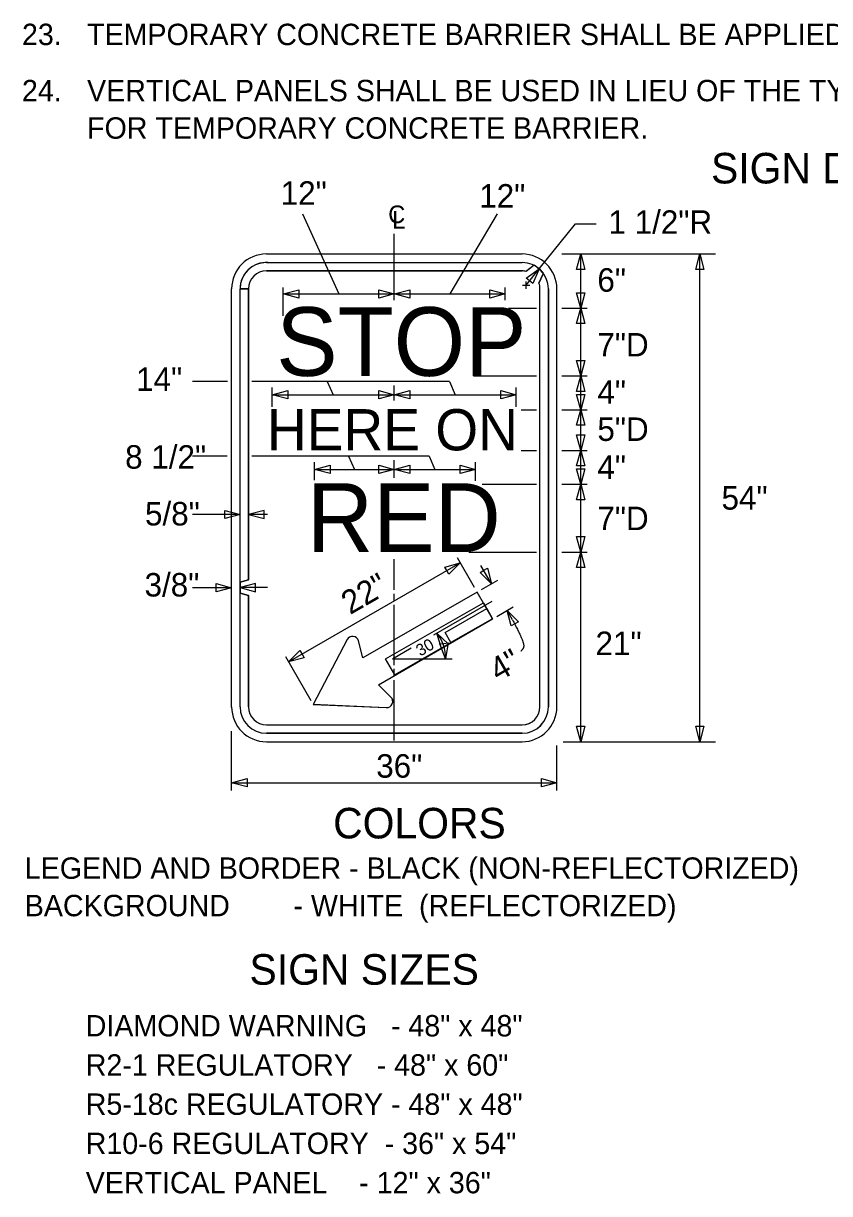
# Model space of a CAD drawing. Extents: x 16520 to 18479, y 5662 to 6927.
# Drawn here: x 17776.7 to 18093.2, y 5956.3 to 6415.8 of the extents above; entities that cross this region are included whole.
import ezdxf

# ---------------------------------------------------------------- set-up
doc = ezdxf.new("R2010")
doc.units = 0
for name, color, linetype in [('MT_SCRATCH_LEVEL_A', 7, 'Continuous'), ('TRAFFIC_SIGNS_PR', 7, 'Continuous'), ('TYPICAL_TEXT_DIMEN_EX', 7, 'Continuous'), ('TYPICAL_TEXT_DIMEN_PR', 7, 'Continuous')]:
    doc.layers.add(name, color=color, linetype=linetype)

msp = doc.modelspace()

# ---------------------------------------------------------------- linework, layer by layer
at = {"layer": 'MT_SCRATCH_LEVEL_A'}
for p, q in [((17922.3, 6307.14), (17922.3, 6333.18)), ((17922.3, 6267.68), (17922.3, 6273.69)), ((17922.3, 6237.32), (17922.3, 6244.25)), ((17922.3, 6193.35), (17922.3, 6205.49)), ((17922.3, 6188.92), (17922.3, 6191.87)), ((17922.3, 6163.79), (17922.3, 6187.44)), ((17922.3, 6159.36), (17922.3, 6162.32)), ((17922.3, 6134.24), (17922.3, 6157.88))]:
    msp.add_line(p, q, dxfattribs=at)
at = {"layer": 'TRAFFIC_SIGNS_PR'}
for p, q in [((17872.12, 6325.27), (17972.55, 6325.27)), ((17872.12, 6321.95), (17872.65, 6321.95)), ((17872.12, 6318.62), (17972.57, 6318.62)), ((17972.57, 6318.62), (17872.12, 6318.62)), ((17872.65, 6321.95), (17972.47, 6321.95)), ((17872.65, 6321.93), (17972.47, 6321.95)), ((17977.27, 6320.83), (17974.08, 6318.36)), ((17977.27, 6320.83), (17974.33, 6318.69)), ((17979.08, 6313.77), (17980.85, 6317.7)), ((17980.62, 6317.24), (17979.08, 6313.77)), ((17858.46, 6147.28), (17858.46, 6311.6)), ((17861.78, 6311.6), (17865.1, 6311.6)), ((17865.11, 6311.6), (17861.78, 6311.6)), ((17861.78, 6147.42), (17861.78, 6311.53)), ((17865.1, 6311.53), (17861.78, 6311.53)), ((17865.1, 6197.27), (17865.1, 6311.53)), ((17979.48, 6147.42), (17979.48, 6311.6)), ((17979.48, 6147.42), (17979.48, 6311.6)), ((17982.81, 6147.42), (17982.81, 6311.6)), ((17982.81, 6311.6), (17982.81, 6147.42)), ((17986.14, 6147.42), (17986.14, 6311.6)), ((17861.79, 6196.38), (17865.1, 6197.27)), ((17861.79, 6193.07), (17861.79, 6195.38)), ((17865.1, 6191.18), (17861.79, 6192.07)), ((17865.1, 6147.42), (17865.1, 6191.18)), ((17954.82, 6192.53), (17910.01, 6166.66)), ((17960.9, 6182), (17954.82, 6192.53)), ((17916.09, 6156.13), (17960.9, 6182)), ((17903.76, 6173.84), (17890.48, 6148.36)), ((17910.01, 6166.66), (17908.27, 6173.33)), ((17920.99, 6151.28), (17916.09, 6156.13)), ((17890.48, 6148.36), (17919.18, 6147.13)), ((17872.12, 6140.4), (17972.52, 6140.4)), ((17872.12, 6140.4), (17972.52, 6140.4)), ((17872.12, 6137.08), (17972.47, 6137.08)), ((17972.47, 6137.08), (17872.12, 6137.08)), ((17872.12, 6133.75), (17930.99, 6133.75)), ((17872.12, 6133.75), (17930.99, 6133.75)), ((17930.99, 6133.75), (17972.47, 6133.75))]:
    msp.add_line(p, q, dxfattribs=at)
msp.add_lwpolyline([(17861.78, 6147.42), (17861.78, 6311.53), (17865.1, 6311.53), (17865.1, 6197.27), (17861.79, 6196.38), (17861.79, 6192.07), (17865.1, 6191.18), (17865.1, 6147.42)], dxfattribs=at)
for points in [[(17960.9, 6182), (17922.52, 6160.01), (17918.9, 6166.33), (17957.28, 6188.32)], [(17960.9, 6182), (17944.56, 6172.65), (17942.24, 6176.7), (17958.58, 6186.05)]]:
    msp.add_lwpolyline(points, close=True, dxfattribs=at)
for centre, radius, start, end in [((17872.12, 6311.6), 13.67, 90, 180), ((17972.46, 6311.6), 13.67, 0, 90), ((17872.12, 6311.6), 10.34, 90, 180), ((17872.12, 6311.6), 10.34, 87.0749, 180), ((17872.12, 6311.6), 7.02, 90, 180), ((17872.12, 6311.6), 7.02, 90, 180), ((17972.46, 6311.6), 10.34, 0.0011, 90), ((17972.46, 6311.6), 10.34, 0, 90), ((17972.46, 6311.6), 7.02, 76.1968, 90), ((17972.68, 6314.86), 3.76, 68.3136, 91.7829), ((17965.42, 6303.66), 20.86, 42.2917, 55.3821), ((17972.46, 6311.6), 10.34, 42.6036, 55.6914), ((17975.26, 6311.94), 4.24, 355.4085, 25.5399), ((17972.46, 6311.6), 7.02, 0.0011, 18.4463), ((17905.91, 6172.71), 2.43, 14.678, 152.4708), ((17919.28, 6149.56), 2.43, 267.5292, 45.322), ((17872.12, 6147.42), 13.67, 180, 270), ((17872.12, 6147.42), 10.34, 180, 270), ((17872.12, 6147.42), 10.35, 180, 270), ((17872.12, 6147.42), 7.02, 180, 270), ((17872.12, 6147.42), 7.02, 180, 270), ((17972.46, 6147.42), 10.34, 270, 0), ((17972.46, 6147.42), 7.02, 270, 0), ((17972.46, 6147.42), 13.67, 270, 0), ((17972.46, 6147.42), 10.35, 270, 0), ((17972.46, 6147.42), 7.02, 270.4693, 0)]:
    msp.add_arc(centre, radius, start, end, dxfattribs=at)
at = {"layer": 'TYPICAL_TEXT_DIMEN_EX'}
for p, q in [((17903.76, 6173.84), (17890.48, 6148.36)), ((17910.01, 6166.66), (17908.27, 6173.33)), ((17916.1, 6156.13), (17921, 6151.28)), ((17919.18, 6147.12), (17890.48, 6148.36))]:
    msp.add_line(p, q, dxfattribs=at)
for centre, start, end in [((17905.91, 6172.71), 14.6782, 152.471), ((17919.29, 6149.56), 267.5295, 45.3222)]:
    msp.add_arc(centre, 2.43, start, end, dxfattribs=at)
at = {"layer": 'TYPICAL_TEXT_DIMEN_PR'}
for p, q in [((17886.21, 6341.01), (17900.52, 6309.57)), ((17962.76, 6341.01), (17944.07, 6309.57)), ((17979.22, 6319.44), (17993.5, 6337.13)), ((17993.5, 6337.13), (18001.59, 6337.13)), ((17988.05, 6325.27), (18048.37, 6325.27)), ((17993.87, 6319.2), (17995.5, 6325.27)), ((17995.5, 6303.99), (17995.5, 6325.27)), ((17995.5, 6325.27), (17997.12, 6319.2)), ((18040.65, 6319.2), (18042.27, 6325.27)), ((18042.27, 6133.75), (18042.27, 6325.27)), ((18042.27, 6325.27), (18043.9, 6319.2)), ((17974.06, 6313.04), (17979.22, 6319.44)), ((17974.15, 6315.74), (17979.22, 6319.44)), ((17979.22, 6319.44), (17976.68, 6313.69)), ((17995.5, 6319.2), (17993.87, 6319.2)), ((17997.12, 6319.2), (17995.5, 6319.2)), ((18042.27, 6319.2), (18040.65, 6319.2)), ((18043.9, 6319.2), (18042.27, 6319.2)), ((17974.06, 6311.56), (17974.06, 6314.51)), ((17975.41, 6314.71), (17974.15, 6315.74)), ((17976.68, 6313.69), (17975.41, 6314.71)), ((17878.74, 6300.98), (17878.74, 6312.05)), ((17878.74, 6309.57), (17884.8, 6311.19)), ((17878.74, 6309.57), (17922.3, 6309.57)), ((17884.8, 6307.94), (17878.74, 6309.57)), ((17884.8, 6311.19), (17884.8, 6309.57)), ((17884.8, 6309.57), (17884.8, 6307.94)), ((17916.23, 6309.57), (17916.23, 6311.19)), ((17916.23, 6311.19), (17922.3, 6309.57)), ((17922.3, 6309.57), (17916.23, 6307.94)), ((17916.23, 6307.94), (17916.23, 6309.57)), ((17922.3, 6309.57), (17928.36, 6311.19)), ((17922.3, 6309.57), (17965.85, 6309.57)), ((17928.36, 6307.94), (17922.3, 6309.57)), ((17928.36, 6311.19), (17928.36, 6309.57)), ((17928.36, 6309.57), (17928.36, 6307.94)), ((17959.78, 6309.57), (17959.78, 6311.19)), ((17959.78, 6311.19), (17965.85, 6309.57)), ((17959.78, 6309.57), (17959.78, 6311.19)), ((17959.78, 6311.19), (17965.85, 6309.57)), ((17965.85, 6309.57), (17959.78, 6307.94)), ((17959.78, 6307.94), (17959.78, 6309.57)), ((17965.85, 6309.57), (17959.78, 6307.94)), ((17959.78, 6307.94), (17959.78, 6309.57)), ((17965.85, 6307.14), (17965.85, 6312.05)), ((17972.58, 6313.04), (17975.54, 6313.04)), ((17995.5, 6303.99), (17993.87, 6310.06)), ((17993.87, 6310.06), (17995.5, 6310.06)), ((17995.5, 6310.06), (17997.12, 6310.06)), ((17997.12, 6310.06), (17995.5, 6303.99)), ((17967.19, 6303.99), (17978.2, 6303.99)), ((17988.05, 6303.99), (17997.98, 6303.99)), ((17993.87, 6297.93), (17995.5, 6303.99)), ((17995.5, 6277.39), (17995.5, 6303.99)), ((17995.5, 6303.99), (17997.12, 6297.93)), ((17995.5, 6297.93), (17993.87, 6297.93)), ((17997.12, 6297.93), (17995.5, 6297.93)), ((17995.5, 6277.39), (17993.87, 6283.46)), ((17993.87, 6283.46), (17995.5, 6283.46)), ((17995.5, 6283.46), (17997.12, 6283.46)), ((17997.12, 6283.46), (17995.5, 6277.39)), ((17953.45, 6277.39), (17978.2, 6277.39)), ((17988.05, 6277.39), (17997.98, 6277.39)), ((17993.87, 6271.32), (17995.5, 6277.39)), ((17995.5, 6264.09), (17995.5, 6277.39)), ((17995.5, 6277.39), (17997.12, 6271.32)), ((17856.87, 6275.15), (17843.07, 6275.15)), ((17944.01, 6275.15), (17866.39, 6275.15)), ((17874.42, 6265.2), (17874.42, 6272.87)), ((17895.99, 6275.15), (17898.35, 6270.01)), ((17944.01, 6275.15), (17946.23, 6270.01)), ((17970.17, 6265.2), (17970.17, 6272.87)), ((17874.42, 6270.01), (17880.48, 6271.64)), ((17874.42, 6270.01), (17922.3, 6270.01)), ((17880.48, 6268.39), (17874.42, 6270.01)), ((17880.48, 6271.64), (17880.48, 6270.01)), ((17880.48, 6270.01), (17880.48, 6268.39)), ((17916.23, 6270.01), (17916.23, 6271.64)), ((17916.23, 6271.64), (17922.3, 6270.01)), ((17922.3, 6270.01), (17916.23, 6268.39)), ((17916.23, 6268.39), (17916.23, 6270.01)), ((17922.3, 6270.01), (17928.36, 6271.64)), ((17922.3, 6270.01), (17970.17, 6270.01)), ((17928.36, 6268.39), (17922.3, 6270.01)), ((17928.36, 6271.64), (17928.36, 6270.01)), ((17928.36, 6270.01), (17928.36, 6268.39)), ((17964.11, 6270.01), (17964.11, 6271.64)), ((17964.11, 6271.64), (17970.17, 6270.01)), ((17970.17, 6270.01), (17964.11, 6268.39)), ((17964.11, 6268.39), (17964.11, 6270.01)), ((17995.5, 6271.32), (17993.87, 6271.32)), ((17995.5, 6264.09), (17993.87, 6270.16)), ((17993.87, 6270.16), (17995.5, 6270.16)), ((17997.12, 6271.32), (17995.5, 6271.32)), ((17995.5, 6270.16), (17997.12, 6270.16)), ((17997.12, 6270.16), (17995.5, 6264.09)), ((17972.18, 6264.09), (17978.2, 6264.09)), ((17988.05, 6264.09), (17997.98, 6264.09)), ((17993.87, 6258.03), (17995.5, 6264.09)), ((17995.5, 6248.13), (17995.5, 6264.09)), ((17995.5, 6264.09), (17997.12, 6258.03)), ((17995.5, 6258.03), (17993.87, 6258.03)), ((17995.5, 6248.13), (17993.87, 6254.2)), ((17993.87, 6254.2), (17995.5, 6254.2)), ((17997.12, 6258.03), (17995.5, 6258.03)), ((17995.5, 6254.2), (17997.12, 6254.2)), ((17997.12, 6254.2), (17995.5, 6248.13)), ((17856.7, 6245.88), (17843.07, 6245.88)), ((17936, 6245.88), (17866.39, 6245.88)), ((17904.28, 6245.88), (17906.67, 6240.67)), ((17936, 6245.88), (17938.26, 6240.67)), ((17972.18, 6248.13), (17978.2, 6248.13)), ((17988.05, 6248.13), (17997.98, 6248.13)), ((17993.87, 6242.07), (17995.5, 6248.13)), ((17995.5, 6234.83), (17995.5, 6248.13)), ((17995.5, 6248.13), (17997.12, 6242.07)), ((17891.04, 6236.44), (17891.04, 6243.53)), ((17891.04, 6240.67), (17897.11, 6242.3)), ((17891.04, 6240.67), (17922.3, 6240.67)), ((17897.11, 6239.05), (17891.04, 6240.67)), ((17897.11, 6242.3), (17897.11, 6240.67)), ((17897.11, 6240.67), (17897.11, 6239.05)), ((17916.23, 6240.67), (17916.23, 6242.3)), ((17916.23, 6242.3), (17922.3, 6240.67)), ((17922.3, 6240.67), (17916.23, 6239.05)), ((17916.23, 6239.05), (17916.23, 6240.67)), ((17922.3, 6240.67), (17928.36, 6242.3)), ((17922.3, 6240.67), (17954.22, 6240.67)), ((17928.36, 6239.05), (17922.3, 6240.67)), ((17928.36, 6242.3), (17928.36, 6240.67)), ((17928.36, 6240.67), (17928.36, 6239.05)), ((17948.15, 6240.67), (17948.15, 6242.3)), ((17948.15, 6242.3), (17954.22, 6240.67)), ((17954.22, 6240.67), (17948.15, 6239.05)), ((17948.15, 6239.05), (17948.15, 6240.67)), ((17954.22, 6236.22), (17954.22, 6243.53)), ((17995.5, 6242.07), (17993.87, 6242.07)), ((17995.5, 6234.83), (17993.87, 6240.9)), ((17993.87, 6240.9), (17995.5, 6240.9)), ((17997.12, 6242.07), (17995.5, 6242.07)), ((17995.5, 6240.9), (17997.12, 6240.9)), ((17997.12, 6240.9), (17995.5, 6234.83)), ((17956.81, 6234.83), (17978.2, 6234.83)), ((17988.05, 6234.83), (17997.98, 6234.83)), ((17993.87, 6228.77), (17995.5, 6234.83)), ((17995.5, 6208.23), (17995.5, 6234.83)), ((17995.5, 6234.83), (17997.12, 6228.77)), ((17995.5, 6228.77), (17993.87, 6228.77)), ((17997.12, 6228.77), (17995.5, 6228.77)), ((17861.79, 6222.98), (17843.07, 6222.98)), ((17855.72, 6222.98), (17855.72, 6224.6)), ((17855.72, 6224.6), (17861.79, 6222.98)), ((17861.79, 6222.98), (17855.72, 6221.35)), ((17855.72, 6221.35), (17855.72, 6222.98)), ((17871.17, 6224.6), (17865.1, 6222.98)), ((17865.1, 6222.98), (17871.17, 6221.35)), ((17872.58, 6222.98), (17865.1, 6222.98)), ((17871.17, 6222.98), (17871.17, 6224.6)), ((17871.17, 6221.35), (17871.17, 6222.98)), ((17995.5, 6208.23), (17993.87, 6214.3)), ((17993.87, 6214.3), (17995.5, 6214.3)), ((17995.5, 6214.3), (17997.12, 6214.3)), ((17997.12, 6214.3), (17995.5, 6208.23)), ((17951.55, 6208.23), (17978.2, 6208.23)), ((17988.05, 6208.23), (17997.98, 6208.23)), ((17993.87, 6202.17), (17995.5, 6208.23)), ((17995.5, 6133.75), (17995.5, 6208.23)), ((17995.5, 6208.23), (17997.12, 6202.17)), ((17880.83, 6165.08), (17948.21, 6203.98)), ((17942.14, 6202.36), (17948.21, 6203.98)), ((17948.21, 6203.98), (17943.77, 6199.54)), ((17953.8, 6194.3), (17947.08, 6205.94)), ((17942.95, 6200.95), (17942.14, 6202.36)), ((17943.77, 6199.54), (17942.95, 6200.95)), ((17956.05, 6200.25), (17957.46, 6201.06)), ((17960.49, 6195.81), (17956.05, 6200.25)), ((17960.49, 6195.81), (17956.33, 6203.01)), ((17957.46, 6201.06), (17958.87, 6201.88)), ((17958.87, 6201.88), (17960.49, 6195.81)), ((17995.5, 6202.17), (17993.87, 6202.17)), ((17997.12, 6202.17), (17995.5, 6202.17)), ((17858.46, 6194.24), (17843.07, 6194.24)), ((17852.39, 6194.24), (17852.39, 6195.86)), ((17852.39, 6195.86), (17858.46, 6194.24)), ((17858.46, 6194.24), (17852.39, 6192.61)), ((17852.39, 6192.61), (17852.39, 6194.24)), ((17867.86, 6195.91), (17861.79, 6194.28)), ((17861.79, 6194.28), (17867.86, 6192.66)), ((17872.58, 6194.28), (17861.79, 6194.28)), ((17867.86, 6194.28), (17867.86, 6195.91)), ((17867.86, 6192.66), (17867.86, 6194.28)), ((17956.5, 6193.5), (17962.9, 6197.2)), ((17937.82, 6175.7), (17960.7, 6188.91)), ((17962.58, 6182.97), (17968.98, 6186.66)), ((17968.66, 6181.66), (17966.57, 6185.28)), ((17968.2, 6179.21), (17966.57, 6185.28)), ((17966.57, 6185.28), (17971.02, 6180.84)), ((17971.02, 6180.84), (17969.61, 6180.02)), ((17940.78, 6170.35), (17938.97, 6176.36)), ((17938.97, 6176.36), (17943.54, 6172.06)), ((17969.61, 6180.02), (17968.2, 6179.21)), ((17940.18, 6172.21), (17941.8, 6172.38)), ((17942.42, 6166.34), (17940.18, 6172.21)), ((17942.16, 6171.2), (17940.78, 6170.35)), ((17941.8, 6172.38), (17943.42, 6172.54)), ((17943.54, 6172.06), (17942.16, 6171.2)), ((17943.42, 6172.54), (17942.42, 6166.34)), ((17889.61, 6149.87), (17879.69, 6167.04)), ((17880.83, 6165.08), (17885.27, 6169.52)), ((17886.89, 6166.71), (17880.83, 6165.08)), ((17885.27, 6169.52), (17886.08, 6168.12)), ((17886.08, 6168.12), (17886.89, 6166.71)), ((17921.62, 6166.34), (17928.98, 6170.59)), ((17921.62, 6166.34), (17945.06, 6166.34)), ((17995.5, 6133.75), (17993.87, 6139.82)), ((17993.87, 6139.82), (17995.5, 6139.82)), ((17995.5, 6139.82), (17997.12, 6139.82)), ((17997.12, 6139.82), (17995.5, 6133.75)), ((18042.27, 6133.75), (18040.65, 6139.82)), ((18040.65, 6139.82), (18042.27, 6139.82)), ((18042.27, 6139.82), (18043.9, 6139.82)), ((18043.9, 6139.82), (18042.27, 6133.75)), ((17858.46, 6114.57), (17858.46, 6137.91)), ((17986.14, 6114.57), (17986.14, 6132.23)), ((17988.58, 6133.75), (18048.37, 6133.75)), ((17858.46, 6117.65), (17864.52, 6119.28)), ((17858.46, 6117.65), (17986.14, 6117.65)), ((17864.52, 6116.03), (17858.46, 6117.65)), ((17864.52, 6119.28), (17864.52, 6117.65)), ((17864.52, 6117.65), (17864.52, 6116.03)), ((17980.07, 6117.65), (17980.07, 6119.28)), ((17980.07, 6119.28), (17986.14, 6117.65)), ((17986.14, 6117.65), (17980.07, 6116.03)), ((17980.07, 6116.03), (17980.07, 6117.65))]:
    msp.add_line(p, q, dxfattribs=at)
msp.add_arc((17928.06, 6167), 14.37, 357.3664, 40.6242, dxfattribs=at)
msp.add_open_spline([(17968.66, 6181.66), (17971.82, 6175.77), (17973.52, 6170.98), (17972.01, 6169.29), (17972.01, 6169.29)], degree=2, dxfattribs=at)

# ---------------------------------------------------------------- texts
at = {"layer": 'TYPICAL_TEXT_DIMEN_EX'}
for s, height, p in [('STOP', 26.972, (17875.97, 6277.41)), ('HERE ON', 16.181, (17872.28, 6248.16)), ('RED', 26.968, (17887.99, 6208.28))]:
    msp.add_text(s, height=height, dxfattribs=at).set_placement(p)
at = {"layer": 'TYPICAL_TEXT_DIMEN_PR'}
for s, height, p in [('23.', 8.4, (17776.14, 6407.29)), ('TEMPORARY CONCRETE BARRIER SHALL BE APPLIED AS PER THE CURRENT STANDARD PLAN.', 8.4, (17801.7, 6407.29)), ('24.', 8.4, (17776.13, 6385.24)), ('VERTICAL PANELS SHALL BE USED IN LIEU OF THE TYPE B HIGH INTENSITY LIGHT SHOWN IN THE STANDARD PLAN ', 8.4, (17801.7, 6385.24)), ('FOR TEMPORARY CONCRETE BARRIER.', 8.4, (17801.7, 6370.54)), ('SIGN DETAIL', 12, (18046.66, 6352.97)), ('12" ', 9.222, (17877.72, 6344.6)), ('12"', 9.222, (17955.66, 6343.48)), ('1 1/2"R', 9.222, (18006.39, 6333.19)), ('6"', 9.222, (18002.04, 6310.47)), ('7"D', 9.222, (18002.04, 6285.04)), ('14"', 9.222, (17820.96, 6271.52)), ('4"', 9.222, (18002.04, 6266.44)), ('5"D', 9.222, (18002.04, 6251.87)), ('8 1/2"', 9.222, (17816.64, 6240.97)), ('4"', 9.222, (18002.04, 6236.98)), ('54"', 9.222, (18050.78, 6224.89)), ('5/8"', 9.222, (17824.44, 6218.67)), ('7"D', 9.222, (18002.04, 6216.83)), ('3/8"', 9.222, (17824.26, 6190.77)), ('21"', 9.222, (18001.32, 6167.78)), ('36" ', 9.222, (17915.22, 6119.64)), ('COLORS', 12, (17898.31, 6095.78)), ('LEGEND AND BORDER - BLACK (NON-REFLECTORIZED)', 8.4, (17777.24, 6079.92)), ('BACKGROUND        - WHITE  (REFLECTORIZED)', 8.4, (17777.24, 6065.22)), ('SIGN SIZES', 12, (17865.46, 6038.33)), ('DIAMOND WARNING   - 48" x 48"', 8.4, (17801.17, 6018.03)), ('R2-1 REGULATORY   - 48" x 60"', 8.4, (17801.17, 6002.63)), ('R5-18c REGULATORY - 48" x 48"', 8.4, (17801.17, 5987.23)), ('R10-6 REGULATORY  - 36" x 54"', 8.4, (17801.17, 5971.83)), ('VERTICAL PANEL    - 12" x 36"', 8.4, (17801.17, 5956.43))]:
    msp.add_text(s, height=height, dxfattribs=at).set_placement(p)
for s, height, rotation, p in [('C', 6.93, 0, (17919.93, 6337.38)), ('L', 6.93, 0, (17921.49, 6335.26)), ('22"', 9.222, 29.9375, (17904.96, 6183.46)), ('30', 4.618, 30, (17932.49, 6167.16)), ('4"', 9.222, 29.9998, (17963.15, 6157.13))]:
    msp.add_text(s, height=height, rotation=rotation, dxfattribs=at).set_placement(p)

doc.saveas('drawing.dxf')
